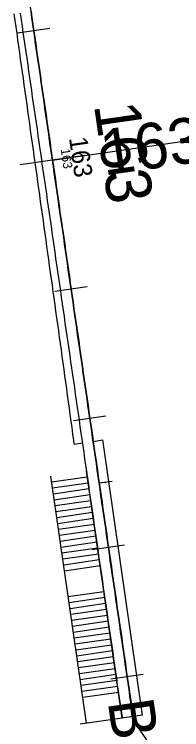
# Model space of a CAD drawing. Extents: x 1823824 to 1861612, y 706975 to 726130.
# Drawn here: x 1826123.4 to 1826149.1, y 715179.3 to 715288.9 of the extents above; entities that cross this region are included whole.
import ezdxf

# ---------------------------------------------------------------- set-up
doc = ezdxf.new("R2010")
doc.units = 0
for name, color, linetype in [('DR_X_Flood_Boundary', 7, 'Continuous'), ('GE_X_CL_10', 7, 'Continuous'), ('GE_X_CL_100', 7, 'Continuous'), ('GE_X_CL_20', 7, 'Continuous'), ('GE_X_CL_200', 7, 'Continuous'), ('GE_X_CL_50', 7, 'Continuous'), ('SC_Scratch3', 7, 'Continuous'), ('SC_Scratch5', 7, 'Continuous'), ('SC_Scratch6', 7, 'Continuous')]:
    doc.layers.add(name, color=color, linetype=linetype)

msp = doc.modelspace()

# ---------------------------------------------------------------- linework, layer by layer
at = {"layer": 'DR_X_Flood_Boundary'}
for p, q in [((1826123.8, 715304.42), (1826141.7, 715180.65)), ((1826135.51, 715223.5), (1826137, 715223.71)), ((1826143.1, 715181.54), (1826137, 715223.71)), ((1826132.63, 715223.08), (1826133.86, 715223.26)), ((1826134.52, 715180.29), (1826129.04, 715218.14)), ((1826134.62, 715218.02), (1826129.17, 715217.23)), ((1826139.96, 715181.07), (1826134.49, 715218.93)), ((1826134.75, 715217.11), (1826129.3, 715216.33)), ((1826134.88, 715216.21), (1826129.43, 715215.42)), ((1826135.01, 715215.3), (1826129.56, 715214.51)), ((1826135.14, 715214.39), (1826129.69, 715213.6)), ((1826135.27, 715213.49), (1826129.82, 715212.7)), ((1826135.41, 715212.58), (1826129.96, 715211.79)), ((1826135.54, 715211.67), (1826130.09, 715210.88)), ((1826135.67, 715210.76), (1826130.22, 715209.98)), ((1826135.8, 715209.86), (1826130.35, 715209.07)), ((1826135.93, 715208.95), (1826130.48, 715208.16)), ((1826136.06, 715208.04), (1826130.61, 715207.25)), ((1826136.19, 715207.14), (1826130.74, 715206.35)), ((1826136.32, 715206.23), (1826130.87, 715205.44)), ((1826136.46, 715205.32), (1826131, 715204.53)), ((1826136.59, 715204.41), (1826131.14, 715203.63)), ((1826137.16, 715200.45), (1826131.71, 715199.67)), ((1826137.29, 715199.55), (1826131.84, 715198.76)), ((1826137.42, 715198.64), (1826131.97, 715197.85)), ((1826137.55, 715197.73), (1826132.1, 715196.95)), ((1826137.68, 715196.83), (1826132.23, 715196.04)), ((1826137.81, 715195.92), (1826132.36, 715195.13)), ((1826137.95, 715195.01), (1826132.49, 715194.22)), ((1826138.08, 715194.1), (1826132.63, 715193.32)), ((1826138.21, 715193.2), (1826132.76, 715192.41)), ((1826138.34, 715192.29), (1826132.89, 715191.5)), ((1826138.47, 715191.38), (1826133.02, 715190.6)), ((1826138.6, 715190.48), (1826133.15, 715189.69)), ((1826138.73, 715189.57), (1826133.28, 715188.78)), ((1826138.86, 715188.66), (1826133.41, 715187.87)), ((1826139, 715187.76), (1826133.55, 715186.97)), ((1826139.13, 715186.85), (1826133.68, 715186.06)), ((1826139.26, 715185.94), (1826133.81, 715185.15)), ((1826139.39, 715185.03), (1826133.94, 715184.25)), ((1826139.96, 715181.07), (1826133.53, 715180.14)), ((1826141.7, 715180.65), (1826295.66, 714955.3))]:
    msp.add_line(p, q, dxfattribs=at)
msp.add_lwpolyline([(1826143.1, 715181.54), (1826141.62, 715181.32), (1826139.96, 715181.07)], dxfattribs=at)
at = {"layer": 'GE_X_CL_10'}
for p, q in [((1826129.27, 715266.61), (1826130.26, 715266.75)), ((1826136.43, 715217.12), (1826137.42, 715217.26))]:
    msp.add_line(p, q, dxfattribs=at)
at = {"layer": 'GE_X_CL_100'}
msp.add_line((1826129.27, 715266.61), (1826139.17, 715268.04), dxfattribs=at)
at = {"layer": 'GE_X_CL_20'}
for p, q in [((1826129.27, 715266.61), (1826131.25, 715266.89)), ((1826136.43, 715217.12), (1826138.41, 715217.41))]:
    msp.add_line(p, q, dxfattribs=at)
at = {"layer": 'GE_X_CL_200'}
msp.add_line((1826129.27, 715266.61), (1826149.06, 715269.47), dxfattribs=at)
at = {"layer": 'GE_X_CL_50'}
msp.add_line((1826129.27, 715266.61), (1826134.22, 715267.32), dxfattribs=at)
at = {"layer": 'SC_Scratch3'}
for points in [[(1826125.99, 715289.37), (1826126.14, 715288.38), (1826126.28, 715287.39), (1826126.42, 715286.4), (1826126.57, 715285.41), (1826126.71, 715284.42), (1826126.85, 715283.43), (1826127, 715282.44), (1826127.14, 715281.45), (1826127.28, 715280.46), (1826127.43, 715279.47), (1826127.57, 715278.48), (1826127.71, 715277.49), (1826127.86, 715276.51), (1826128, 715275.52), (1826128.14, 715274.53), (1826128.29, 715273.54), (1826128.43, 715272.55), (1826128.57, 715271.56), (1826128.72, 715270.57), (1826128.86, 715269.58), (1826128.96, 715268.85), (1826129, 715268.59), (1826129.15, 715267.6), (1826129.29, 715266.61), (1826129.33, 715266.29), (1826129.43, 715265.62), (1826129.57, 715264.63), (1826129.72, 715263.64), (1826129.86, 715262.65), (1826130, 715261.66), (1826130.15, 715260.67), (1826130.29, 715259.68), (1826130.43, 715258.69), (1826130.58, 715257.7), (1826130.72, 715256.71), (1826130.86, 715255.72), (1826131.01, 715254.73), (1826131.15, 715253.74), (1826131.29, 715252.75), (1826131.44, 715251.76), (1826131.58, 715250.77), (1826131.72, 715249.78), (1826131.87, 715248.79), (1826132.01, 715247.8), (1826132.15, 715246.81), (1826132.3, 715245.82), (1826132.44, 715244.84), (1826132.58, 715243.85), (1826132.73, 715242.86), (1826132.87, 715241.87), (1826133.01, 715240.88), (1826133.16, 715239.89), (1826133.3, 715238.9), (1826133.44, 715237.91), (1826133.59, 715236.92), (1826133.73, 715235.93), (1826133.87, 715234.94), (1826134.01, 715233.95), (1826134.16, 715232.96), (1826134.3, 715231.97), (1826134.44, 715230.98), (1826134.59, 715229.99), (1826134.73, 715229), (1826134.87, 715228.01), (1826135.02, 715227.02), (1826135.16, 715226.03), (1826135.3, 715225.04), (1826135.45, 715224.05), (1826135.59, 715223.06), (1826135.73, 715222.07), (1826135.88, 715221.08), (1826136.02, 715220.09), (1826136.16, 715219.1)], [(1826132.71, 715242.85), (1826132.57, 715243.84), (1826132.43, 715244.83), (1826132.29, 715245.82), (1826132.14, 715246.81), (1826132, 715247.8), (1826131.86, 715248.79), (1826131.71, 715249.78), (1826131.57, 715250.77), (1826131.43, 715251.76), (1826131.28, 715252.75), (1826131.14, 715253.74), (1826131, 715254.73), (1826130.85, 715255.72), (1826130.71, 715256.71), (1826130.57, 715257.7), (1826130.42, 715258.69), (1826130.28, 715259.68), (1826130.14, 715260.67), (1826129.99, 715261.66), (1826129.85, 715262.65), (1826129.71, 715263.64), (1826129.56, 715264.63), (1826129.42, 715265.62), (1826129.32, 715266.29), (1826129.28, 715266.61), (1826129.14, 715267.6), (1826128.99, 715268.59), (1826128.95, 715268.85), (1826128.85, 715269.58), (1826128.71, 715270.57), (1826128.56, 715271.56), (1826128.42, 715272.55), (1826128.28, 715273.53), (1826128.13, 715274.52), (1826127.99, 715275.51), (1826127.85, 715276.5), (1826127.7, 715277.49), (1826127.56, 715278.48), (1826127.42, 715279.47), (1826127.27, 715280.46), (1826127.13, 715281.45), (1826126.99, 715282.44), (1826126.84, 715283.43), (1826126.7, 715284.42), (1826126.56, 715285.41), (1826126.42, 715286.4), (1826126.27, 715287.39), (1826126.13, 715288.38), (1826125.99, 715289.37)], [(1826129.95, 715242.45), (1826129.81, 715243.44), (1826129.68, 715244.44), (1826129.54, 715245.43), (1826129.4, 715246.42), (1826129.26, 715247.41), (1826129.12, 715248.4), (1826128.99, 715249.39), (1826128.85, 715250.38), (1826128.71, 715251.37), (1826128.57, 715252.36), (1826128.43, 715253.35), (1826128.3, 715254.34), (1826128.16, 715255.33), (1826128.02, 715256.32), (1826127.88, 715257.31), (1826127.74, 715258.3), (1826127.6, 715259.29), (1826127.46, 715260.28), (1826127.32, 715261.27), (1826127.19, 715262.26), (1826127.05, 715263.25), (1826126.91, 715264.24), (1826126.77, 715265.23), (1826126.67, 715265.91), (1826126.63, 715266.22), (1826126.49, 715267.21), (1826126.35, 715268.2), (1826126.31, 715268.47), (1826126.21, 715269.19), (1826126.07, 715270.18), (1826125.93, 715271.17), (1826125.79, 715272.17), (1826125.65, 715273.16), (1826125.52, 715274.15), (1826125.38, 715275.14), (1826125.24, 715276.13), (1826125.1, 715277.12), (1826124.96, 715278.11), (1826124.82, 715279.1), (1826124.68, 715280.09), (1826124.54, 715281.08), (1826124.4, 715282.07), (1826124.26, 715283.06), (1826124.12, 715284.05), (1826123.99, 715285.04), (1826123.85, 715286.03), (1826123.71, 715287.02), (1826123.57, 715288.01), (1826123.43, 715289)], [(1826124.33, 715289.13), (1826124.48, 715288.14), (1826124.62, 715287.15), (1826124.76, 715286.16), (1826124.91, 715285.17), (1826125.05, 715284.18), (1826125.19, 715283.19), (1826125.34, 715282.2), (1826125.48, 715281.21), (1826125.62, 715280.22), (1826125.76, 715279.23), (1826125.91, 715278.24), (1826126.05, 715277.25), (1826126.19, 715276.26), (1826126.34, 715275.28), (1826126.48, 715274.29), (1826126.62, 715273.3), (1826126.77, 715272.31), (1826126.91, 715271.32), (1826127.05, 715270.33), (1826127.2, 715269.34), (1826127.3, 715268.61), (1826127.34, 715268.35), (1826127.48, 715267.36), (1826127.63, 715266.37), (1826127.67, 715266.05), (1826127.77, 715265.38), (1826127.91, 715264.39), (1826128.06, 715263.4), (1826128.2, 715262.41), (1826128.34, 715261.42), (1826128.48, 715260.43), (1826128.63, 715259.44), (1826128.77, 715258.45), (1826128.91, 715257.46), (1826129.06, 715256.47), (1826129.2, 715255.48), (1826129.34, 715254.49), (1826129.49, 715253.5), (1826129.63, 715252.51), (1826129.77, 715251.52), (1826129.92, 715250.53), (1826130.06, 715249.54), (1826130.2, 715248.55), (1826130.35, 715247.56), (1826130.49, 715246.57), (1826130.63, 715245.58), (1826130.78, 715244.59), (1826130.92, 715243.6), (1826131.06, 715242.61), (1826131.2, 715241.63), (1826131.35, 715240.64), (1826131.49, 715239.65), (1826131.63, 715238.66), (1826131.78, 715237.67), (1826131.92, 715236.68), (1826132.06, 715235.69), (1826132.21, 715234.7), (1826132.35, 715233.71), (1826132.49, 715232.72), (1826132.64, 715231.73), (1826132.78, 715230.74), (1826132.92, 715229.75), (1826133.07, 715228.76), (1826133.21, 715227.77), (1826133.35, 715226.78), (1826133.5, 715225.79), (1826133.64, 715224.8), (1826133.78, 715223.81), (1826133.93, 715222.82), (1826134.07, 715221.83), (1826134.21, 715220.84), (1826134.35, 715219.85), (1826134.5, 715218.86)], [(1826132.63, 715223.08), (1826132.55, 715223.63), (1826132.41, 715224.62), (1826132.28, 715225.61), (1826132.14, 715226.6), (1826132.01, 715227.6), (1826131.87, 715228.59), (1826131.74, 715229.58), (1826131.6, 715230.57), (1826131.47, 715231.56), (1826131.33, 715232.55), (1826131.19, 715233.54), (1826131.06, 715234.53), (1826130.92, 715235.52), (1826130.78, 715236.51), (1826130.64, 715237.5), (1826130.5, 715238.49), (1826130.37, 715239.48), (1826130.23, 715240.47), (1826130.09, 715241.46), (1826129.95, 715242.45)], [(1826136.16, 715219.1), (1826136.31, 715218.11), (1826136.45, 715217.12), (1826136.59, 715216.13), (1826136.74, 715215.14), (1826136.88, 715214.15), (1826137.02, 715213.16), (1826137.17, 715212.18), (1826137.31, 715211.19), (1826137.45, 715210.2), (1826137.59, 715209.21), (1826137.74, 715208.22), (1826137.88, 715207.23), (1826138.02, 715206.24), (1826138.17, 715205.25), (1826138.31, 715204.26), (1826138.45, 715203.27), (1826138.6, 715202.28), (1826138.74, 715201.29), (1826138.88, 715200.3), (1826139.03, 715199.31), (1826139.17, 715198.32), (1826139.31, 715197.33), (1826139.46, 715196.34), (1826139.6, 715195.35), (1826139.74, 715194.36), (1826139.89, 715193.37), (1826140.03, 715192.38), (1826140.17, 715191.39), (1826140.32, 715190.4), (1826140.46, 715189.41), (1826140.6, 715188.42), (1826140.74, 715187.43), (1826140.89, 715186.44), (1826141.03, 715185.45), (1826141.17, 715184.46), (1826141.32, 715183.47), (1826141.46, 715182.48), (1826141.59, 715181.49), (1826141.45, 715182.48), (1826141.3, 715183.47), (1826141.16, 715184.46), (1826141.02, 715185.45), (1826140.88, 715186.44), (1826140.73, 715187.43), (1826140.59, 715188.42), (1826140.45, 715189.41), (1826140.3, 715190.4), (1826140.16, 715191.39), (1826140.02, 715192.38), (1826139.87, 715193.37), (1826139.73, 715194.36), (1826139.59, 715195.35), (1826139.44, 715196.34), (1826139.3, 715197.33), (1826139.16, 715198.32), (1826139.01, 715199.31), (1826138.87, 715200.3), (1826138.73, 715201.29), (1826138.58, 715202.28), (1826138.44, 715203.27), (1826138.3, 715204.26), (1826138.15, 715205.25), (1826138.01, 715206.24), (1826137.87, 715207.22), (1826137.73, 715208.21), (1826137.58, 715209.2), (1826137.44, 715210.19), (1826137.3, 715211.18), (1826137.15, 715212.17), (1826137.01, 715213.16), (1826136.87, 715214.15), (1826136.72, 715215.14), (1826136.58, 715216.13), (1826136.44, 715217.12), (1826136.29, 715218.11), (1826136.15, 715219.1), (1826136.01, 715220.09), (1826135.86, 715221.08), (1826135.72, 715222.07), (1826135.58, 715223.06), (1826135.43, 715224.05), (1826135.29, 715225.04), (1826135.15, 715226.03), (1826135.01, 715227.02), (1826134.86, 715228.01), (1826134.72, 715229), (1826134.58, 715229.99), (1826134.43, 715230.98), (1826134.29, 715231.97), (1826134.15, 715232.96), (1826134, 715233.95), (1826133.86, 715234.94), (1826133.72, 715235.93), (1826133.57, 715236.92), (1826133.43, 715237.91), (1826133.29, 715238.9), (1826133.14, 715239.88), (1826133, 715240.87), (1826132.86, 715241.86), (1826132.71, 715242.85)], [(1826134.5, 715218.86), (1826134.64, 715217.87), (1826134.78, 715216.88), (1826134.93, 715215.89), (1826135.07, 715214.9), (1826135.21, 715213.91), (1826135.36, 715212.92), (1826135.5, 715211.93), (1826135.64, 715210.94), (1826135.79, 715209.95), (1826135.93, 715208.97), (1826136.07, 715207.98), (1826136.22, 715206.99), (1826136.36, 715206), (1826136.5, 715205.01), (1826136.65, 715204.02), (1826136.79, 715203.03), (1826136.93, 715202.04), (1826137.07, 715201.05), (1826137.22, 715200.06), (1826137.36, 715199.07), (1826137.5, 715198.08), (1826137.65, 715197.09), (1826137.79, 715196.1), (1826137.93, 715195.11), (1826138.08, 715194.12), (1826138.22, 715193.13), (1826138.36, 715192.14), (1826138.51, 715191.15), (1826138.65, 715190.16), (1826138.79, 715189.17), (1826138.94, 715188.18), (1826139.08, 715187.19), (1826139.22, 715186.2), (1826139.37, 715185.21), (1826139.51, 715184.22), (1826139.65, 715183.23), (1826139.8, 715182.24), (1826139.94, 715181.25)], [(1826139.94, 715181.25), (1826139.96, 715181.09)], [(1826141.62, 715181.32), (1826141.59, 715181.49)]]:
    msp.add_lwpolyline(points, dxfattribs=at)
at = {"layer": 'SC_Scratch5'}
for points in [[(1826128.88, 715286.76), (1826123.93, 715286.04)], [(1826134.22, 715267.32), (1826124.32, 715265.89)], [(1826134.61, 715247.17), (1826129.66, 715246.45)], [(1826137.47, 715227.38), (1826132.52, 715226.66)], [(1826140.33, 715207.58), (1826135.38, 715206.87)], [(1826143.2, 715187.79), (1826138.25, 715187.07)]]:
    msp.add_lwpolyline(points, dxfattribs=at)

# ---------------------------------------------------------------- texts
at = {"layer": 'GE_X_CL_10'}
msp.add_text('163', height=1.4, rotation=278.2313, dxfattribs=at).set_placement((1826130.54, 715268.29))
at = {"layer": 'GE_X_CL_20'}
msp.add_text('163', height=2.8, rotation=278.2313, dxfattribs=at).set_placement((1826131.81, 715269.98))
at = {"layer": 'GE_X_CL_50'}
msp.add_text('163', height=7, rotation=278.2313, dxfattribs=at).set_placement((1826135.63, 715275.04))
at = {"layer": 'SC_Scratch5'}
msp.add_text('163+00', height=7, rotation=8.2313, dxfattribs=at).set_placement((1826137.19, 715264.22))
at = {"layer": 'SC_Scratch6'}
msp.add_text('B', height=7, rotation=278.2313, dxfattribs=at).set_placement((1826137.74, 715183.62))

doc.saveas('drawing.dxf')
